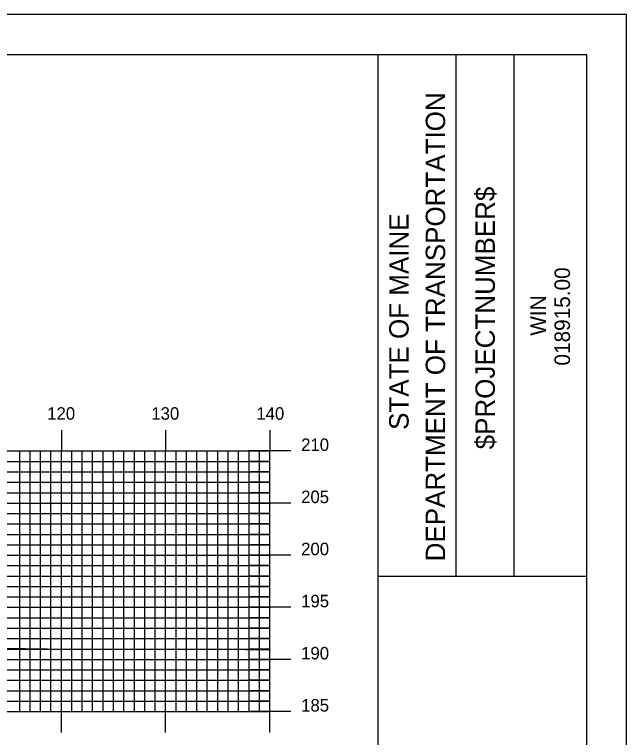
# Model space of a CAD drawing. Extents: x 1814915 to 1815259, y 442591 to 442811.
# Drawn here: x 1815196.5 to 1815255.2, y 442741.2 to 442810.5 of the extents above; entities that cross this region are included whole.
import ezdxf

# ---------------------------------------------------------------- set-up
doc = ezdxf.new("R2010")
doc.units = 0
for name, color, linetype in [('BORDER', 7, 'Continuous'), ('H_V ANNOTATION', 7, 'Continuous'), ('MAJOR', 7, 'Continuous'), ('MINOR', 7, 'Continuous'), ('PLOT BOUNDARY', 7, 'Continuous'), ('S_Roadway_Centerline', 7, 'Continuous')]:
    doc.layers.add(name, color=color, linetype=linetype)

msp = doc.modelspace()

# ---------------------------------------------------------------- linework, layer by layer
at = {"layer": 'BORDER'}
for p, q in [((1815231.421, 442596.665), (1815231.421, 442806.665)), ((1815238.878, 442756.659), (1815238.878, 442806.659)), ((1815244.468, 442756.659), (1815244.468, 442806.659)), ((1815231.422, 442756.653), (1815251.421, 442756.653))]:
    msp.add_line(p, q, dxfattribs=at)
msp.add_lwpolyline([(1814931.421, 442596.665), (1815251.421, 442596.665), (1815251.421, 442806.665), (1814931.421, 442806.665)], close=True, dxfattribs=at)
at = {"layer": 'MAJOR'}
for p, q in [((1815201.021, 442770.669), (1815201.021, 442768.665)), ((1815211.021, 442770.669), (1815211.021, 442768.665)), ((1815221.021, 442770.669), (1815221.021, 442768.665)), ((1814941.021, 442768.665), (1815221.021, 442768.665)), ((1814941.021, 442768.665), (1815221.021, 442768.665)), ((1815201.021, 442743.665), (1815201.021, 442768.665)), ((1815211.021, 442743.665), (1815211.021, 442768.665)), ((1815223.025, 442768.665), (1815219.017, 442768.665)), ((1815221.021, 442743.665), (1815221.021, 442768.665)), ((1815221.021, 442743.665), (1815221.021, 442768.665)), ((1814941.021, 442763.665), (1815221.021, 442763.665)), ((1815223.025, 442763.665), (1815219.017, 442763.665)), ((1814941.021, 442758.665), (1815221.021, 442758.665)), ((1815223.025, 442758.665), (1815219.017, 442758.665)), ((1814941.021, 442753.665), (1815221.021, 442753.665)), ((1815223.025, 442753.665), (1815219.017, 442753.665)), ((1814941.021, 442748.665), (1815221.021, 442748.665)), ((1815223.025, 442748.665), (1815219.017, 442748.665)), ((1814941.021, 442743.665), (1815221.021, 442743.665)), ((1814941.021, 442743.665), (1815221.021, 442743.665)), ((1815201.021, 442741.661), (1815201.021, 442743.665)), ((1815211.021, 442741.661), (1815211.021, 442743.665)), ((1815223.025, 442743.665), (1815219.017, 442743.665)), ((1815221.021, 442741.661), (1815221.021, 442743.665))]:
    msp.add_line(p, q, dxfattribs=at)
at = {"layer": 'MINOR'}
for p, q in [((1815197.021, 442743.665), (1815197.021, 442768.665)), ((1815198.021, 442743.665), (1815198.021, 442768.665)), ((1815199.021, 442743.665), (1815199.021, 442768.665)), ((1815200.021, 442743.665), (1815200.021, 442768.665)), ((1815202.021, 442743.665), (1815202.021, 442768.665)), ((1815203.021, 442743.665), (1815203.021, 442768.665)), ((1815204.021, 442743.665), (1815204.021, 442768.665)), ((1815205.021, 442743.665), (1815205.021, 442768.665)), ((1815206.021, 442743.665), (1815206.021, 442768.665)), ((1815207.021, 442743.665), (1815207.021, 442768.665)), ((1815208.021, 442743.665), (1815208.021, 442768.665)), ((1815209.021, 442743.665), (1815209.021, 442768.665)), ((1815210.021, 442743.665), (1815210.021, 442768.665)), ((1815212.021, 442743.665), (1815212.021, 442768.665)), ((1815213.021, 442743.665), (1815213.021, 442768.665)), ((1815214.021, 442743.665), (1815214.021, 442768.665)), ((1815215.021, 442743.665), (1815215.021, 442768.665)), ((1815216.021, 442743.665), (1815216.021, 442768.665)), ((1815217.021, 442743.665), (1815217.021, 442768.665)), ((1815218.021, 442743.665), (1815218.021, 442768.665)), ((1815219.021, 442743.665), (1815219.021, 442768.665)), ((1815220.021, 442743.665), (1815220.021, 442768.665)), ((1814941.021, 442767.665), (1815221.021, 442767.665)), ((1815221.021, 442767.665), (1815219.017, 442767.665)), ((1814941.021, 442766.665), (1815221.021, 442766.665)), ((1815221.021, 442766.665), (1815219.017, 442766.665)), ((1814941.021, 442765.665), (1815221.021, 442765.665)), ((1815221.021, 442765.665), (1815219.017, 442765.665)), ((1814941.021, 442764.665), (1815221.021, 442764.665)), ((1815221.021, 442764.665), (1815219.017, 442764.665)), ((1814941.021, 442762.665), (1815221.021, 442762.665)), ((1815221.021, 442762.665), (1815219.017, 442762.665)), ((1814941.021, 442761.665), (1815221.021, 442761.665)), ((1815221.021, 442761.665), (1815219.017, 442761.665)), ((1814941.021, 442760.665), (1815221.021, 442760.665)), ((1815221.021, 442760.665), (1815219.017, 442760.665)), ((1814941.021, 442759.665), (1815221.021, 442759.665)), ((1815221.021, 442759.665), (1815219.017, 442759.665)), ((1814941.021, 442757.665), (1815221.021, 442757.665)), ((1815221.021, 442757.665), (1815219.017, 442757.665)), ((1814941.021, 442756.665), (1815221.021, 442756.665)), ((1815221.021, 442756.665), (1815219.017, 442756.665)), ((1814941.021, 442755.665), (1815221.021, 442755.665)), ((1815221.021, 442755.665), (1815219.017, 442755.665)), ((1814941.021, 442754.665), (1815221.021, 442754.665)), ((1815221.021, 442754.665), (1815219.017, 442754.665)), ((1814941.021, 442752.665), (1815221.021, 442752.665)), ((1815221.021, 442752.665), (1815219.017, 442752.665)), ((1814941.021, 442751.665), (1815221.021, 442751.665)), ((1815221.021, 442751.665), (1815219.017, 442751.665)), ((1814941.021, 442750.665), (1815221.021, 442750.665)), ((1815221.021, 442750.665), (1815219.017, 442750.665)), ((1814941.021, 442749.665), (1815221.021, 442749.665)), ((1815221.021, 442749.665), (1815219.017, 442749.665)), ((1814941.021, 442747.665), (1815221.021, 442747.665)), ((1815221.021, 442747.665), (1815219.017, 442747.665)), ((1814941.021, 442746.665), (1815221.021, 442746.665)), ((1815221.021, 442746.665), (1815219.017, 442746.665)), ((1814941.021, 442745.665), (1815221.021, 442745.665)), ((1815221.021, 442745.665), (1815219.017, 442745.665)), ((1814941.021, 442744.665), (1815221.021, 442744.665)), ((1815221.021, 442744.665), (1815219.017, 442744.665))]:
    msp.add_line(p, q, dxfattribs=at)
at = {"layer": 'PLOT BOUNDARY'}
msp.add_lwpolyline([(1814915.234, 442590.547), (1815255.234, 442590.547), (1815255.234, 442810.547), (1814915.234, 442810.547)], close=True, dxfattribs=at)
at = {"layer": 'S_Roadway_Centerline'}
msp.add_lwpolyline([(1815126.402, 442749.71), (1815137.574, 442749.683), (1815150.597, 442749.63), (1815154.07, 442749.585), (1815167.94, 442749.887), (1815169.729, 442749.89), (1815182.088, 442749.867), (1815187.773, 442749.84), (1815188.896, 442749.837), (1815204.004, 442749.615), (1815215.497, 442749.683), (1815220.278, 442749.598), (1815221.021, 442749.604)], dxfattribs=at)

# ---------------------------------------------------------------- texts
at = {"layer": 'BORDER'}
for s, height, p in [('DEPARTMENT OF TRANSPORTATION', 1.86351, (1815237.834, 442758.077)), ('$PROJECTNUMBER$', 1.86351, (1815242.604, 442768.823)), ('STATE OF MAINE', 1.86351, (1815234.331, 442770.689)), ('018915.00', 1.4905, (1815249.812, 442776.861)), ('WIN', 1.4905, (1815247.494, 442779.725))]:
    msp.add_text(s, height=height, rotation=90, dxfattribs=at).set_placement(p)
at = {"layer": 'H_V ANNOTATION'}
for s, p in [('120', (1815199.661, 442771.665)), ('130', (1815209.651, 442771.665)), ('140', (1815219.725, 442771.665)), ('210', (1815224.021, 442768.665)), ('205', (1815224.021, 442763.665)), ('200', (1815224.021, 442758.665)), ('195', (1815224.021, 442753.665)), ('190', (1815224.021, 442748.665)), ('185', (1815224.021, 442743.665))]:
    msp.add_text(s, height=1.2, dxfattribs=at).set_placement(p)

doc.saveas('drawing.dxf')
